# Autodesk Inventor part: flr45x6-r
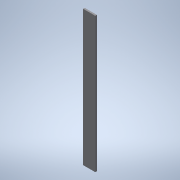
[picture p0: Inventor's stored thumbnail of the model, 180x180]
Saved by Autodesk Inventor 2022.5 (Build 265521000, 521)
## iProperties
Created: 2016-12
Part Number: flr45x6-r
Material: 一般
Document SubType Name: Modeling
Designer: imaocorp
Density: 1 g/cm^3
Appearance: 既定
Author: imaocorp
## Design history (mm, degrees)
node "flr45x6-r.x_t1"
node "flr45x6-r"
node "Base1"
